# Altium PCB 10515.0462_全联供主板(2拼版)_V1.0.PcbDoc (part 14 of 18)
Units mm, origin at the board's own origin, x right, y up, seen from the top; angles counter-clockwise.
Board outline 282 x 198 mm, 2 copper layers (Top Layer, Bottom Layer); 716 components, 0 nets, 2364 pads, 1800 vias.
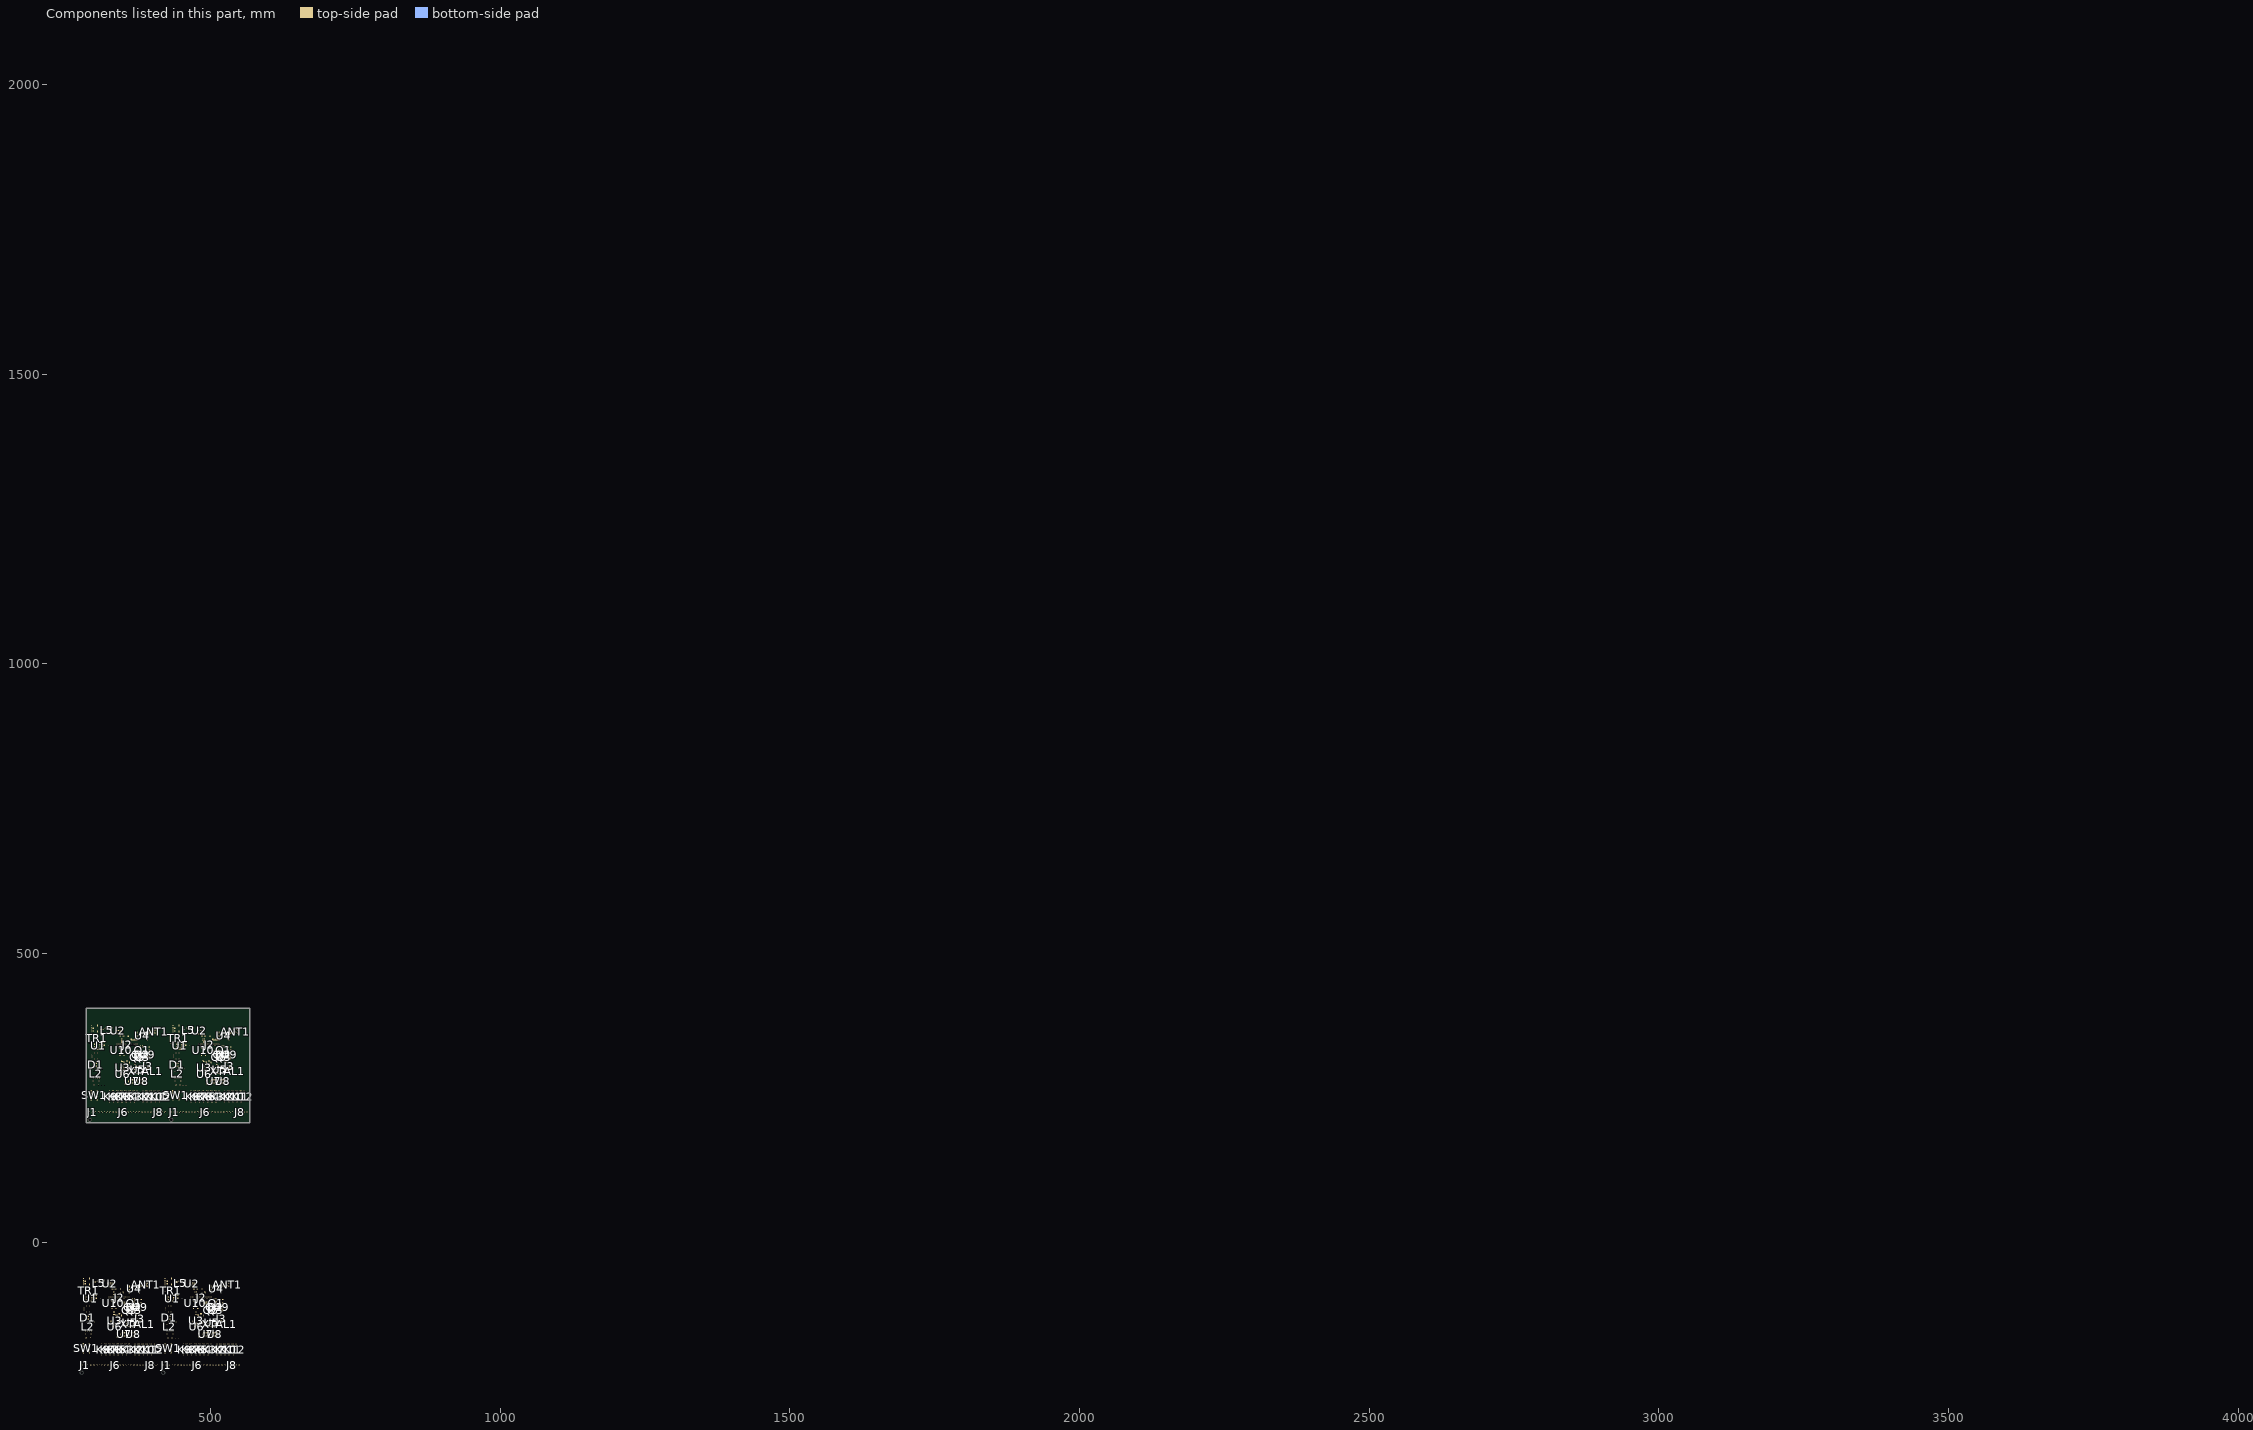
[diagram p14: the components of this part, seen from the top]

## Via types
v1: diameter 0.7, hole 0.4, Top Layer to Bottom Layer, tented both sides, 1800 vias

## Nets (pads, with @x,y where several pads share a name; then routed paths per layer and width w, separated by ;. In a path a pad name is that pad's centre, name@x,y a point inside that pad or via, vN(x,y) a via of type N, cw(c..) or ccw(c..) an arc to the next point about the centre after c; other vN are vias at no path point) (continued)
copper on no net: (continued)
  Top Layer w1.5: 440.573,-186.462 441.272,-185.763 ; 441.71,225.611 442.645,226.546 442.645,235.02 ; 442.391,371.661 444.03,371.661 445.439,373.069 ; 442.426,-218.858 443.961,-217.323 ; 442.426,-218.858 445.496,-218.858 ; 442.645,370.275 444.296,370.275 445.439,371.418 445.439,373.069 ; 442.645,370.275 445.439,373.069 ; 443.089,264.357 443.089,263.151 444.128,262.112 ; 443.089,264.357 443.089,267.088 ; 443.665,-189.256 444.764,-189.256 ; 443.875,-176.556 443.875,-173.299 ; 443.875,-176.556 444.002,-176.683 444.129,-176.683 446.288,-178.842 ; 443.875,-176.556 443.875,-174.778 ; 443.875,-176.556 448.066,-180.747 ; 443.875,-174.778 448.066,-178.969 ; 443.875,-174.778 443.875,-173.299 ; 443.875,-173.299 443.875,-164.491 ; 443.875,-164.491 444.88,-165.496 444.88,-174.016 ; 443.961,-217.323 445.496,-218.858 ; 444.128,260.42 445.566,258.982 445.566,258.515 445.693,258.642 445.693,262.96 ; 444.128,260.42 445.693,261.985 445.693,262.96 ; 444.128,260.42 444.128,267.573 ; 444.128,260.42 444.128,262.112 ; 444.128,262.112 445.058,263.042 445.058,266.643 ; 444.128,267.573 445.058,266.643 ; 444.88,-174.016 453.204,-182.34 ; 445.058,266.643 445.693,266.008 445.693,262.96 ; 445.121,-76.353 445.121,-78.361 446.034,-79.274 457.845,-79.274 459.623,-81.052 ; 445.121,-76.353 445.121,-73.489 445.971,-74.338 445.971,-76.48 ; 445.121,-76.353 445.121,-77.091 445.971,-77.94 ; 445.306,327.973 445.306,328.359 446.328,329.381 ; 445.496,-218.858 452.638,-218.858 ; 445.496,-218.858 446.247,-219.609 ; 445.802,-183.817 445.891,-183.817 447.453,-182.255 ; 445.971,-77.94 445.971,-76.48 ; 445.971,-76.48 445.971,-76.67 447.812,-78.512 458.734,-78.512 459.623,-79.401 459.623,-81.052 ; 446.247,-219.609 461.675,-219.609 ; 446.288,-178.842 447.453,-180.007 447.453,-182.255 ; 446.328,329.381 449.376,332.429 451.675,332.429 452.24,332.994 ; 446.98,272.029 447.921,271.088 451.408,271.088 452.348,272.029 ; 446.98,272.029 452.348,272.029 ; 447.59,219.145 449.749,216.986 ; 447.59,219.145 447.59,220.034 ; 447.59,220.034 447.59,225.611 447.59,225.995 447.09,225.495 447.09,218.256 448.36,216.986 449.749,216.986 ; 447.59,220.034 449.887,217.737 456.054,217.737 ; 448.066,-183.502 448.066,-180.62 ; 448.066,-183.502 450.761,-183.502 451.484,-182.779 449.325,-180.62 448.066,-180.62 ; 448.066,-180.747 448.066,-180.62 ; 448.066,-180.62 448.066,-178.969 ; 448.233,302.965 451.027,302.965 453.948,300.044 ; 448.233,302.965 449.376,302.965 452.297,300.044 453.948,300.044 ; 449.749,216.986 459.876,216.986 ; 452.638,-218.858 453.961,-217.536 ; 452.638,-218.858 455.496,-218.858 ; 453.781,-81.814 454.67,-81.814 ; 453.948,300.044 453.948,298.774 453.313,298.139 448.599,298.139 446.328,295.868 447.994,295.868 449.249,297.123 452.551,297.123 454.075,298.647 454.075,299.917 453.948,300.044 ; 453.961,-217.536 453.961,-217.323 ; 453.961,-217.323 455.496,-218.858 ; 454.202,250.133 454.9,250.832 ; 455.051,-186.252 459.856,-186.252 467.016,-186.252 474.175,-186.252 481.335,-186.252 488.495,-186.252 495.597,-186.252 495.724,-186.125 510.456,-186.125 517.568,-186.125 516.508,-185.065 ; 455.496,-218.858 462.426,-218.858 ; 456.054,217.737 457.59,219.272 ; 456.054,217.737 459.125,217.737 ; 457.294,247.339 458.393,247.339 ; 457.38,-156.871 457.38,-155.855 ; 457.504,260.039 457.504,263.296 ; 457.504,260.039 457.631,259.912 457.758,259.912 459.917,257.753 ; 457.504,260.039 457.504,261.817 ; 457.504,260.039 461.695,255.848 ; 457.504,261.817 461.695,257.626 ; 457.504,261.817 457.504,263.296 ; 457.504,263.296 457.504,272.104 ; 457.504,272.104 458.509,271.1 458.509,262.579 ; 457.59,219.272 459.125,217.737 ; 458.509,262.579 466.833,254.255 ; 458.75,360.242 458.75,358.234 459.663,357.321 471.474,357.321 473.252,355.543 ; 458.75,360.242 458.75,363.106 459.599,362.257 459.599,360.115 ; 458.75,360.242 458.75,359.504 459.599,358.655 ; 459.125,217.737 466.267,217.737 ; 459.125,217.737 459.876,216.986 ; 459.431,252.778 459.519,252.778 461.082,254.341 ; 459.599,358.655 459.599,360.115 ; 459.599,360.115 459.599,359.925 461.441,358.083 472.363,358.083 473.252,357.194 473.252,355.543 ; 459.876,216.986 475.304,216.986 ; 459.917,257.753 461.082,256.588 461.082,254.341 ; 461.675,-219.609 501.548,-219.609 ; 461.675,-219.609 462.426,-218.858 ; 461.695,253.093 461.695,255.975 ; 461.695,253.093 464.39,253.093 465.113,253.816 462.954,255.975 461.695,255.975 ; 461.695,255.848 461.695,255.975 ; 461.695,255.975 461.695,257.626 ; 462.426,-218.858 465.496,-218.858 ; 462.426,-218.858 463.961,-217.323 ; 463.433,-200.443 467.016,-196.861 467.016,-196.368 ; 463.961,-217.323 465.496,-218.858 ; 465.496,-218.858 472.426,-218.858 ; 466.267,217.737 467.59,219.06 ; 466.267,217.737 469.125,217.737 ; 467.41,354.781 468.299,354.781 ; 467.59,219.06 467.59,219.272 ; 467.59,219.272 469.125,217.737 ; 468.68,250.343 473.485,250.343 480.645,250.343 487.804,250.343 494.964,250.343 502.124,250.343 509.226,250.343 509.353,250.47 524.085,250.47 531.197,250.47 530.137,251.53 ; 469.125,217.737 476.054,217.737 ; 471.009,279.724 471.009,280.74 ; 472.426,-218.858 475.496,-218.858 ; 472.426,-218.858 473.961,-217.323 ; 473.961,-217.323 475.496,-218.858 ; 475.304,216.986 515.177,216.986 ; 475.304,216.986 476.054,217.737 ; 475.496,-218.858 482.356,-218.858 ; 476.054,217.737 479.125,217.737 ; 476.054,217.737 477.59,219.272 ; 477.062,236.152 480.645,239.735 480.645,240.227 ; 477.59,219.272 479.125,217.737 ; 479.125,217.737 486.054,217.737 ; 482.356,-218.858 485.623,-218.858 ; 482.356,-218.858 483.961,-217.254 ; 483.961,-217.254 483.961,-217.196 ; 483.961,-217.196 485.623,-218.858 ; 485.623,-218.858 492.426,-218.858 ; 486.054,217.737 489.125,217.737 ; 486.054,217.737 487.59,219.272 ; 487.59,219.272 489.125,217.737 ; 489.125,217.737 495.985,217.737 ; 492.426,-218.858 495.496,-218.858 ; 492.426,-218.858 493.961,-217.323 ; 493.961,-217.323 495.496,-218.858 ; 495.496,-218.858 502.299,-218.858 ; 495.985,217.737 499.252,217.737 ; 495.985,217.737 497.59,219.342 ; 497.59,219.342 497.59,219.399 ; 497.59,219.399 499.252,217.737 ; 499.252,217.737 506.054,217.737 ; 501.548,-219.609 506.105,-219.609 ; 501.548,-219.609 502.299,-218.858 ; 502.299,-218.858 505.355,-218.858 ; 502.299,-218.858 503.961,-217.196 ; 503.961,-217.465 503.961,-217.196 ; 503.961,-217.465 505.355,-218.858 ; 505.355,-218.858 512.235,-218.858 513.961,-217.132 ; 505.355,-218.858 506.105,-219.609 ; 506.054,217.737 509.125,217.737 ; 506.054,217.737 507.59,219.272 ; 506.105,-219.609 512.963,-219.609 513.961,-218.611 513.961,-217.132 ; 507.59,219.272 509.125,217.737 ; 509.125,217.737 515.927,217.737 ; 515.177,216.986 519.734,216.986 ; 515.177,216.986 515.927,217.737 ; 515.927,217.737 518.983,217.737 ; 515.927,217.737 517.59,219.399 ; 517.59,219.131 517.59,219.399 ; 517.59,219.131 518.983,217.737 ; 518.983,217.737 525.864,217.737 527.59,219.463 ; 518.983,217.737 519.734,216.986 ; 519.734,216.986 526.592,216.986 527.59,217.984 527.59,219.463 ; 302.338,-81.912 cw(c302.575,-82.149) 302.575,-81.814 ccw(c302.575,-82.149) 302.338,-81.912 ; 315.967,354.683 cw(c316.204,354.446) 316.204,354.781 ccw(c316.204,354.446) 315.967,354.683 ; 443.338,-81.912 cw(c443.575,-82.149) 443.575,-81.814 ccw(c443.575,-82.149) 443.338,-81.912 ; 456.967,354.683 cw(c457.204,354.446) 457.204,354.781 ccw(c457.204,354.446) 456.967,354.683
  Bottom Layer w0.2: v1@339.147,-110.212 ccw(c338.721,-109.785) 339.324,-109.785 ccw(c339.928,-109.785) v1@339.501,-110.212 ; v1@339.147,-108.661 cw(c338.721,-109.088) 339.324,-109.088 cw(c339.928,-109.088) v1@339.501,-108.661 ; v1(339.324,-110.389) v1(339.324,-108.484) ; v1@340.544,-110.212 ccw(c340.118,-109.785) 340.721,-109.785 ccw(c341.325,-109.785) v1@340.898,-110.212 ; v1@340.544,-107.899 cw(c340.118,-108.326) 340.721,-108.326 cw(c341.325,-108.326) v1@340.898,-107.899 ; v1(340.721,-110.389) v1(340.721,-107.722) ; v1@341.433,-107.391 cw(c341.007,-107.818) 341.61,-107.818 cw(c342.214,-107.818) v1@341.787,-107.391 ; 341.61,-109.962 ccw(c342.164,-109.962) v1@341.772,-110.354 ; 341.61,-109.479 ccw(c342.647,-109.479) v1@341.914,-110.212 ; v1(341.61,-107.214) 341.61,-110.262 v1(341.737,-110.389) ; v1(342.372,-107.722) 342.753,-108.103 ; v1(342.372,-91.593) 343.134,-90.831 351.605,-90.831 352.005,-90.431 352.005,-82.341 v1@352.786,-81.56 ; v1@342.372,-91.343 ccw(c342.372,-90.739) 342.799,-91.166 ccw(c343.226,-91.593) v1@342.622,-91.593 ; v1@342.393,-107.971 cw(c342.431,-108.425) 342.753,-108.103 ; v1@342.576,-111.609 ccw(c342.15,-111.182) 342.753,-111.182 ccw(c343.357,-111.182) v1@342.93,-111.609 ; v1@342.621,-107.743 ccw(c343.075,-107.781) 342.753,-108.103 ; v1(342.753,-111.786) 342.753,-108.103 ; v1@343.543,-91.872 ccw(c343.477,-91.72) 343.642,-91.72 ; v1(343.642,-92.101) 343.642,-91.72 ; v1@343.689,-92.085 cw(c344.184,-91.917) 343.815,-91.547 ; v1@343.742,-91.872 cw(c343.807,-91.72) 343.642,-91.72 ; v1@343.846,-111.609 ccw(c343.113,-110.876) 344.15,-110.876 ; v1@343.879,-92.021 cw(c344.524,-91.802) 344.042,-91.32 ; v1@343.973,-107.518 cw(c343.547,-107.945) 344.15,-107.945 cw(c344.754,-107.945) v1@344.327,-107.518 ; v1@343.988,-111.751 ccw(c343.596,-111.359) 344.15,-111.359 ; v1@344.15,-111.659 v1(344.15,-107.341) ; v1(345.547,-112.929) 345.928,-112.548 ; v1@345.568,-112.68 ccw(c345.606,-112.226) 345.928,-112.548 ; v1@345.751,-106.629 cw(c345.325,-107.056) 345.928,-107.056 cw(c346.532,-107.056) v1@346.105,-106.629 ; v1@345.796,-112.908 cw(c346.25,-112.87) 345.928,-112.548 ; v1(345.928,-106.452) 345.928,-112.548 ; v1(345.928,-92.101) 346.309,-91.72 ; v1@345.949,-91.852 ccw(c345.987,-91.398) 346.309,-91.72 ; v1@346.177,-92.08 cw(c346.631,-92.042) 346.309,-91.72 ; v1@352.409,-81.687 cw(c351.806,-81.687) 352.232,-82.114 cw(c352.659,-82.541) v1@352.659,-81.937 ; v1@352.776,326.383 ccw(c352.349,326.81) 352.953,326.81 ccw(c353.556,326.81) v1@353.13,326.383 ; v1@352.776,327.935 cw(c352.349,327.508) 352.953,327.508 cw(c353.556,327.508) v1@353.13,327.935 ; v1(352.953,326.206) v1(352.953,328.111) ; v1(353.294,-82.322) 353.04,-82.322 352.405,-82.957 352.405,-90.939 352.024,-91.32 344.042,-91.32 ; v1@353.929,-82.957 353.914,-82.972 353.152,-82.972 352.913,-83.211 352.913,-91.466 352.659,-91.72 346.309,-91.72 ; v1@354.173,326.383 ccw(c353.746,326.81) 354.35,326.81 ccw(c354.953,326.81) v1@354.527,326.383 ; v1@354.173,328.697 cw(c353.746,328.27) 354.35,328.27 cw(c354.953,328.27) v1@354.527,328.697 ; v1(354.35,326.206) v1(354.35,328.873) ; v1@355.062,329.205 cw(c354.635,328.778) 355.239,328.778 cw(c355.842,328.778) v1@355.416,329.205 ; 355.239,326.634 ccw(c355.793,326.634) v1@355.401,326.242 ; 355.239,327.117 ccw(c356.276,327.117) v1@355.543,326.383 ; v1(355.239,329.381) 355.239,326.333 v1(355.366,326.206) ; v1(356.001,328.873) 356.382,328.492 ; v1(356.001,345.002) 356.763,345.764 365.234,345.764 365.634,346.164 365.634,354.254 v1@366.415,355.035 ; v1@356.001,345.252 ccw(c356.001,345.856) 356.428,345.429 ccw(c356.854,345.002) v1@356.251,345.002 ; v1@356.022,328.624 cw(c356.06,328.17) 356.382,328.493 ; v1@356.205,324.986 ccw(c355.778,325.413) 356.382,325.413 ccw(c356.985,325.413) v1@356.559,324.986 ; v1@356.25,328.853 ccw(c356.704,328.815) 356.382,328.493 ; v1(356.382,324.809) 356.382,328.492 ; v1@357.171,344.724 ccw(c357.106,344.875) 357.271,344.875 ccw(c357.436,344.875) v1@357.37,344.724 ; v1(357.271,344.494) 357.271,344.875 357.671,345.275 ; v1@357.318,344.511 cw(c357.813,344.679) 357.444,345.048 ; v1@357.475,324.986 ccw(c356.742,325.72) 357.779,325.72 ; v1@357.508,344.575 cw(c358.152,344.794) 357.671,345.275 ; v1@357.602,329.078 cw(c357.175,328.651) 357.779,328.651 cw(c358.382,328.651) v1@357.956,329.078 ; v1@357.617,324.845 ccw(c357.225,325.237) 357.779,325.237 ; v1@357.779,324.936 v1(357.779,329.254) ; v1(359.176,323.666) 359.557,324.047 v1(359.557,330.143) ; v1@359.197,323.916 ccw(c359.235,324.37) 359.557,324.047 ccw(c359.879,323.725) v1@359.425,323.687 ; v1@359.38,329.967 cw(c358.953,329.54) 359.557,329.54 cw(c360.16,329.54) v1@359.734,329.967 ; v1(359.557,344.494) 359.938,344.875 366.288,344.875 366.542,345.129 366.542,353.384 366.781,353.623 367.543,353.623 v1@367.558,353.638 ; v1@359.578,344.744 ccw(c359.616,345.198) 359.938,344.875 ccw(c360.26,344.553) v1@359.806,344.515 ; v1(365.613,-133.122) 366.263,-132.472 375.28,-132.472 375.515,-132.237 ; v1@365.613,-132.872 ccw(c365.613,-132.268) 366.04,-132.695 ccw(c366.467,-133.122) v1@365.863,-133.122 ; v1@366.038,354.908 cw(c365.434,354.908) 365.861,354.482 cw(c366.288,354.055) v1@366.288,354.658 ; v1@366.806,-133.299 cw(c367.233,-133.726) 367.233,-133.122 cw(c367.233,-132.518) v1@366.806,-132.945 ; v1@366.913,-133.122 379.075,-133.122 379.515,-132.682 ; v1(366.923,354.273) 366.669,354.273 366.034,353.638 366.034,345.656 365.653,345.275 357.671,345.275 ; v1(374.884,-116.104) v1(377.24,-116.104) ; 375.011,-127.267 375.011,-127.218 375.457,-126.772 ; v1@375.061,-116.281 cw(c375.488,-116.708) 375.488,-116.104 cw(c375.488,-115.5) v1@375.061,-115.927 ; 375.225,-131.781 cw(c375.012,-132.237) 375.515,-132.237 ; v1@375.281,-119.964 cw(c374.854,-120.391) 375.457,-120.391 cw(c376.061,-120.391) v1@375.634,-119.964 ; 375.457,-126.961 375.457,-126.772 ; v1(375.457,-119.787) 375.457,-126.772 ; 375.515,-131.285 375.515,-132.237 ; 375.805,-131.781 ccw(c376.018,-132.237) 375.515,-132.237 ; 376.027,-127.267 375.952,-127.267 375.457,-126.772 ; v1(377.043,-119.787) 379.329,-119.787 v1(381.615,-119.787) ; v1@377.063,-116.281 ccw(c376.636,-116.708) 376.636,-116.104 ccw(c376.636,-115.5) v1@377.063,-115.927 ; v1@377.22,-119.964 cw(c377.647,-120.391) 377.647,-119.787 cw(c377.647,-119.183) v1@377.22,-119.61 ; 379.06,-131.674 cw(c378.17,-132.682) 379.515,-132.682 ; 379.192,-131.524 cw(c378.561,-132.239) 379.515,-132.239 cw(c380.469,-132.239) 379.838,-131.524 ; v1(379.242,303.473) 379.892,304.123 388.909,304.123 389.144,304.358 ; v1@379.242,303.723 ccw(c379.242,304.327) 379.669,303.9 ccw(c380.095,303.473) v1@379.492,303.473 ; 379.515,-131.285 379.515,-132.682 ; 379.97,-131.674 ccw(c380.86,-132.682) 379.515,-132.682 ; v1@380.435,303.297 cw(c380.861,302.87) 380.861,303.473 cw(c380.861,304.077) v1@380.435,303.65 ; v1@380.542,303.473 392.704,303.473 393.144,303.913 ; v1@381.438,-119.964 ccw(c381.012,-120.391) 381.012,-119.787 ccw(c381.012,-119.183) v1@381.438,-119.61 ; v1(388.513,320.491) v1(390.868,320.491) ; 388.64,309.328 388.64,309.377 389.086,309.823 ; v1@388.69,320.315 cw(c389.116,319.888) 389.116,320.491 cw(c389.116,321.095) v1@388.69,320.668 ; 388.853,304.814 cw(c388.641,304.358) 389.144,304.358 ; v1@388.909,316.632 cw(c388.483,316.205) 389.086,316.205 cw(c389.69,316.205) v1@389.263,316.632 ; 389.086,309.635 389.086,309.823 ; v1(389.086,316.808) 389.086,309.823 ; 389.144,305.31 389.144,304.358 ; 389.434,304.814 ccw(c389.646,304.358) 389.144,304.358 ; 389.656,309.328 389.581,309.328 389.086,309.823 ; v1(390.672,316.808) 392.958,316.808 v1(395.244,316.808) ; v1@390.692,320.315 ccw(c390.265,319.888) 390.265,320.491 ccw(c390.265,321.095) v1@390.692,320.668 ; v1@390.849,316.632 cw(c391.275,316.205) 391.275,316.808 cw(c391.275,317.412) v1@390.849,316.985 ; 392.689,304.922 cw(c391.799,303.913) 393.144,303.913 ; 392.821,305.072 cw(c392.19,304.357) 393.144,304.357 cw(c394.097,304.357) 393.466,305.072 ; 393.144,305.31 393.144,303.913 ; 393.599,304.922 ccw(c394.489,303.913) 393.144,303.913 ; v1@395.067,316.632 ccw(c394.64,316.205) 394.64,316.808 ccw(c394.64,317.412) v1@395.067,316.985 ; v1@480.147,-110.212 ccw(c479.721,-109.785) 480.324,-109.785 ccw(c480.928,-109.785) v1@480.501,-110.212 ; v1@480.147,-108.661 cw(c479.721,-109.088) 480.324,-109.088 cw(c480.928,-109.088) v1@480.501,-108.661 ; v1(480.324,-110.389) v1(480.324,-108.484) ; v1@481.544,-110.212 ccw(c481.118,-109.785) 481.721,-109.785 ccw(c482.325,-109.785) v1@481.898,-110.212 ; v1@481.544,-107.899 cw(c481.118,-108.326) 481.721,-108.326 cw(c482.325,-108.326) v1@481.898,-107.899 ; v1(481.721,-110.389) v1(481.721,-107.722) ; v1@482.433,-107.391 cw(c482.007,-107.818) 482.61,-107.818 cw(c483.214,-107.818) v1@482.787,-107.391 ; 482.61,-109.962 ccw(c483.164,-109.962) v1@482.772,-110.354 ; 482.61,-109.479 ccw(c483.647,-109.479) v1@482.914,-110.212 ; v1(482.61,-107.214) 482.61,-110.262 v1(482.737,-110.389) ; v1(483.372,-107.722) 483.753,-108.103 ; v1(483.372,-91.593) 484.134,-90.831 492.605,-90.831 493.005,-90.431 493.005,-82.341 v1@493.786,-81.56 ; v1@483.372,-91.343 ccw(c483.372,-90.739) 483.799,-91.166 ccw(c484.226,-91.593) v1@483.622,-91.593 ; v1@483.393,-107.971 cw(c483.431,-108.425) 483.753,-108.103 ; v1@483.576,-111.609 ccw(c483.15,-111.182) 483.753,-111.182 ccw(c484.357,-111.182) v1@483.93,-111.609 ; v1@483.621,-107.743 ccw(c484.075,-107.781) 483.753,-108.103 ; v1(483.753,-111.786) 483.753,-108.103 ; v1@484.543,-91.872 ccw(c484.477,-91.72) 484.642,-91.72 ; v1(484.642,-92.101) 484.642,-91.72 ; v1@484.689,-92.085 cw(c485.184,-91.917) 484.815,-91.547 ; v1@484.742,-91.872 cw(c484.807,-91.72) 484.642,-91.72 ; v1@484.846,-111.609 ccw(c484.113,-110.876) 485.15,-110.876 ; v1@484.879,-92.021 cw(c485.524,-91.802) 485.042,-91.32 ; v1@484.973,-107.518 cw(c484.547,-107.945) 485.15,-107.945 cw(c485.754,-107.945) v1@485.327,-107.518 ; v1@484.988,-111.751 ccw(c484.596,-111.359) 485.15,-111.359 ; v1@485.15,-111.659 v1(485.15,-107.341) ; v1(486.547,-112.929) 486.928,-112.548 ; v1@486.568,-112.68 ccw(c486.606,-112.226) 486.928,-112.548 ; v1@486.751,-106.629 cw(c486.325,-107.056) 486.928,-107.056 cw(c487.532,-107.056) v1@487.105,-106.629 ; v1@486.796,-112.908 cw(c487.25,-112.87) 486.928,-112.548 ; v1(486.928,-106.452) 486.928,-112.548 ; v1(486.928,-92.101) 487.309,-91.72 ; v1@486.949,-91.852 ccw(c486.987,-91.398) 487.309,-91.72 ; v1@487.177,-92.08 cw(c487.631,-92.042) 487.309,-91.72 ; v1@493.409,-81.687 cw(c492.806,-81.687) 493.232,-82.114 cw(c493.659,-82.541) v1@493.659,-81.937 ; v1@493.776,326.383 ccw(c493.349,326.81) 493.953,326.81 ccw(c494.556,326.81) v1@494.13,326.383 ; v1@493.776,327.935 cw(c493.349,327.508) 493.953,327.508 cw(c494.556,327.508) v1@494.13,327.935 ; v1(493.953,326.206) v1(493.953,328.111) ; v1(494.294,-82.322) 494.04,-82.322 493.405,-82.957 493.405,-90.939 493.024,-91.32 485.042,-91.32 ; v1@494.929,-82.957 494.914,-82.972 494.152,-82.972 493.913,-83.211 493.913,-91.466 493.659,-91.72 487.309,-91.72 ; v1@495.173,326.383 ccw(c494.746,326.81) 495.35,326.81 ccw(c495.953,326.81) v1@495.527,326.383 ; v1@495.173,328.697 cw(c494.746,328.27) 495.35,328.27 cw(c495.953,328.27) v1@495.527,328.697 ; v1(495.35,326.206) v1(495.35,328.873) ; v1@496.062,329.205 cw(c495.635,328.778) 496.239,328.778 cw(c496.842,328.778) v1@496.416,329.205 ; 496.239,326.634 ccw(c496.793,326.634) v1@496.401,326.242 ; 496.239,327.117 ccw(c497.276,327.117) v1@496.543,326.383 ; v1(496.239,329.381) 496.239,326.333 v1(496.366,326.206) ; v1(497.001,328.873) 497.382,328.492 ; v1(497.001,345.002) 497.763,345.764 506.234,345.764 506.634,346.164 506.634,354.254 v1@507.415,355.035 ; v1@497.001,345.252 ccw(c497.001,345.856) 497.428,345.429 ccw(c497.854,345.002) v1@497.251,345.002 ; v1@497.022,328.624 cw(c497.06,328.17) 497.382,328.493 ; v1@497.205,324.986 ccw(c496.778,325.413) 497.382,325.413 ccw(c497.985,325.413) v1@497.559,324.986 ; v1@497.25,328.853 ccw(c497.704,328.815) 497.382,328.493 ; v1(497.382,324.809) 497.382,328.492 ; v1@498.171,344.724 ccw(c498.106,344.875) 498.271,344.875 ccw(c498.436,344.875) v1@498.37,344.724 ; v1(498.271,344.494) 498.271,344.875 498.671,345.275 ; v1@498.318,344.511 cw(c498.813,344.679) 498.444,345.048 ; v1@498.475,324.986 ccw(c497.742,325.72) 498.779,325.72 ; v1@498.508,344.575 cw(c499.152,344.794) 498.671,345.275 ; v1@498.602,329.078 cw(c498.175,328.651) 498.779,328.651 cw(c499.382,328.651) v1@498.956,329.078 ; v1@498.617,324.845 ccw(c498.225,325.237) 498.779,325.237 ; v1@498.779,324.936 v1(498.779,329.254) ; v1(500.176,323.666) 500.557,324.047 v1(500.557,330.143) ; v1@500.197,323.916 ccw(c500.235,324.37) 500.557,324.047 ccw(c500.879,323.725) v1@500.425,323.687 ; v1@500.38,329.967 cw(c499.953,329.54) 500.557,329.54 cw(c501.16,329.54) v1@500.734,329.967 ; v1(500.557,344.494) 500.938,344.875 507.288,344.875 507.542,345.129 507.542,353.384 507.781,353.623 508.543,353.623 v1@508.558,353.638 ; v1@500.578,344.744 ccw(c500.616,345.198) 500.938,344.875 ccw(c501.26,344.553) v1@500.806,344.515 ; v1(506.613,-133.122) 507.263,-132.472 516.28,-132.472 516.515,-132.237 ; v1@506.613,-132.872 ccw(c506.613,-132.268) 507.04,-132.695 ccw(c507.467,-133.122) v1@506.863,-133.122 ; v1@507.038,354.908 cw(c506.434,354.908) 506.861,354.482 cw(c507.288,354.055) v1@507.288,354.658 ; v1@507.806,-133.299 cw(c508.233,-133.726) 508.233,-133.122 cw(c508.233,-132.518) v1@507.806,-132.945 ; v1@507.913,-133.122 520.075,-133.122 520.515,-132.682 ; v1(507.923,354.273) 507.669,354.273 507.034,353.638 507.034,345.656 506.653,345.275 498.671,345.275 ; v1(515.884,-116.104) v1(518.24,-116.104) ; 516.011,-127.267 516.011,-127.218 516.457,-126.772 ; v1@516.061,-116.281 cw(c516.488,-116.708) 516.488,-116.104 cw(c516.488,-115.5) v1@516.061,-115.927 ; 516.225,-131.781 cw(c516.012,-132.237) 516.515,-132.237 ; v1@516.281,-119.964 cw(c515.854,-120.391) 516.457,-120.391 cw(c517.061,-120.391) v1@516.634,-119.964 ; 516.457,-126.961 516.457,-126.772 ; v1(516.457,-119.787) 516.457,-126.772 ; 516.515,-131.285 516.515,-132.237 ; 516.805,-131.781 ccw(c517.018,-132.237) 516.515,-132.237 ; 517.027,-127.267 516.952,-127.267 516.457,-126.772 ; v1(518.043,-119.787) 520.329,-119.787 v1(522.615,-119.787) ; v1@518.063,-116.281 ccw(c517.636,-116.708) 517.636,-116.104 ccw(c517.636,-115.5) v1@518.063,-115.927 ; v1@518.22,-119.964 cw(c518.647,-120.391) 518.647,-119.787 cw(c518.647,-119.183) v1@518.22,-119.61 ; 520.06,-131.674 cw(c519.17,-132.682) 520.515,-132.682 ; 520.192,-131.524 cw(c519.561,-132.239) 520.515,-132.239 cw(c521.469,-132.239) 520.838,-131.524 ; v1(520.242,303.473) 520.892,304.123 529.909,304.123 530.144,304.358 ; v1@520.242,303.723 ccw(c520.242,304.327) 520.669,303.9 ccw(c521.095,303.473) v1@520.492,303.473 ; 520.515,-131.285 520.515,-132.682 ; 520.97,-131.674 ccw(c521.86,-132.682) 520.515,-132.682 ; v1@521.435,303.297 cw(c521.861,302.87) 521.861,303.473 cw(c521.861,304.077) v1@521.435,303.65 ; v1@521.542,303.473 533.704,303.473 534.144,303.913 ; v1@522.438,-119.964 ccw(c522.012,-120.391) 522.012,-119.787 ccw(c522.012,-119.183) v1@522.438,-119.61 ; v1(529.513,320.491) v1(531.868,320.491) ; 529.64,309.328 529.64,309.377 530.086,309.823 ; v1@529.69,320.315 cw(c530.116,319.888) 530.116,320.491 cw(c530.116,321.095) v1@529.69,320.668 ; 529.853,304.814 cw(c529.641,304.358) 530.144,304.358 ; v1@529.909,316.632 cw(c529.483,316.205) 530.086,316.205 cw(c530.69,316.205) v1@530.263,316.632 ; 530.086,309.635 530.086,309.823 ; v1(530.086,316.808) 530.086,309.823 ; 530.144,305.31 530.144,304.358 ; 530.434,304.814 ccw(c530.646,304.358) 530.144,304.358 ; 530.656,309.328 530.581,309.328 530.086,309.823 ; v1(531.672,316.808) 533.958,316.808 v1(536.244,316.808) ; v1@531.692,320.315 ccw(c531.265,319.888) 531.265,320.491 ccw(c531.265,321.095) v1@531.692,320.668 ; v1@531.849,316.632 cw(c532.275,316.205) 532.275,316.808 cw(c532.275,317.412) v1@531.849,316.985 ; 533.689,304.922 cw(c532.799,303.913) 534.144,303.913 ; 533.821,305.072 cw(c533.19,304.357) 534.144,304.357 cw(c535.097,304.357) 534.466,305.072 ; 534.144,305.31 534.144,303.913 ; 534.599,304.922 ccw(c535.489,303.913) 534.144,303.913 ; v1@536.067,316.632 ccw(c535.64,316.205) 535.64,316.808 ccw(c535.64,317.412) v1@536.067,316.985 ; 343.642,-91.72 344.042,-91.32 ; 484.642,-91.72 485.042,-91.32
  Bottom Layer w0.3: v1(329.545,-132.36) 347.833,-132.36 348.341,-131.852 v1(348.341,-129.439) ; v1@329.687,-132.501 cw(c330.028,-132.843) 330.028,-132.36 cw(c330.028,-131.877) v1@329.687,-132.219 ; v1(343.174,304.235) 361.462,304.235 361.97,304.743 v1(361.97,307.156) ; v1@343.315,304.094 cw(c343.657,303.753) 343.657,304.235 cw(c343.657,304.718) v1@343.315,304.377 ; v1@348.2,-129.58 cw(c347.858,-129.922) 348.341,-129.922 cw(c348.824,-129.922) v1@348.483,-129.58 ; v1@361.828,307.015 cw(c361.487,306.674) 361.97,306.674 cw(c362.453,306.674) v1@362.111,307.015 ; v1(470.545,-132.36) 488.833,-132.36 489.341,-131.852 v1(489.341,-129.439) ; v1@470.687,-132.501 cw(c471.028,-132.843) 471.028,-132.36 cw(c471.028,-131.877) v1@470.687,-132.219 ; v1(484.174,304.235) 502.462,304.235 502.97,304.743 v1(502.97,307.156) ; v1@484.315,304.094 cw(c484.657,303.753) 484.657,304.235 cw(c484.657,304.718) v1@484.315,304.377 ; v1@489.2,-129.58 cw(c488.858,-129.922) 489.341,-129.922 cw(c489.824,-129.922) v1@489.483,-129.58 ; v1@502.828,307.015 cw(c502.487,306.674) 502.97,306.674 cw(c503.453,306.674) v1@503.111,307.015
  Bottom Layer w0.45: v1(323.195,-70.892) 323.335,-71.032 326.31,-71.032 328.355,-68.987 v1(328.656,-68.987) ; v1@323.284,-70.804 ccw(c323.835,-70.252) 323.835,-71.032 ; v1(324.211,-67.717) 325.608,-67.717 325.989,-68.098 v1(325.989,-70.257) ; 327.929,-69.413 cw(c328.656,-70.14) v1@328.656,-69.112 ; v1@328.694,-69.008 v1(333.101,-69.008) ; v1@328.745,-68.899 ccw(c329.01,-68.634) 329.01,-69.008 ; v1(329.672,-136.193) 336.172,-136.193 336.694,-136.715 v1(336.694,-138.112) ; 333.491,-136.193 v1(333.491,-134.13) 333.491,-133.368 333.661,-133.197 v1(342.447,-133.197) ; v1@336.53,-140.234 347.833,-140.234 348.722,-141.123 350.528,-141.123 v1(350.895,-141.49) 348.708,-141.49 347.706,-140.488 v1(336.403,-140.488) 336.657,-140.234 ; v1(336.824,365.703) 336.964,365.563 339.939,365.563 341.984,367.608 v1(342.285,367.608) ; v1@336.912,365.792 ccw(c337.464,366.343) 337.464,365.563 ; v1(337.84,368.878) 339.237,368.878 339.618,368.497 v1(339.618,366.338) ; 341.558,367.182 cw(c342.285,366.455) v1@342.285,367.483 ; v1@342.323,367.587 v1(346.73,367.587) ; v1@342.373,367.697 ccw(c342.638,367.962) 342.638,367.587 ; v1(343.301,300.403) 349.801,300.403 350.323,299.881 v1(350.323,298.484) ; v1@345.928,-126.645 345.928,-126.899 346.309,-127.28 v1(352.278,-127.28) v1(355.072,-127.28) v1@363.547,-127.28 ; 346.944,-127.28 346.436,-126.772 v1(345.928,-126.772) 346.182,-127.026 362.819,-127.026 ; 347.119,300.403 v1(347.119,302.466) 347.119,303.228 347.29,303.399 v1(356.076,303.399) ; 349.707,-141.123 cw(c349.707,-142.678) v1@350.807,-141.578 ; v1@350.159,296.361 361.462,296.361 362.351,295.472 364.157,295.472 v1(364.524,295.105) 362.337,295.105 361.335,296.107 v1(350.032,296.107) 350.286,296.361 ; 351.897,-134.164 cw(c353.066,-134.164) v1@352.24,-133.337 ; 352.024,-128.155 352.15,-128.155 352.926,-128.931 ; 352.138,-143.001 352.138,-142.62 ; v1(352.151,-133.249) v1@352.138,-133.262 ; 352.926,-128.155 352.926,-128.931 ; 353.675,-142.406 353.415,-142.145 ; 353.675,-128.282 353.026,-128.931 352.926,-128.931 ; 355.162,-142.145 cw(c355.162,-142.949) v1@355.73,-142.381 ; 355.242,-142.406 ccw(c355.242,-141.716) v1@355.73,-142.204 ; v1@355.906,-142.381 cw(c356.474,-142.949) 356.474,-142.145 ; v1@355.906,-142.204 ccw(c356.394,-141.716) 356.394,-142.406 ; 358.441,-142.406 353.18,-142.406 352.926,-142.152 352.926,-141.377 ; 358.454,-142.393 365.486,-142.393 366.003,-142.909 366.003,-147.084 ; v1@359.557,309.95 359.557,309.696 359.938,309.315 v1(365.907,309.315) v1(368.701,309.315) v1@377.176,309.315 ; 360.573,309.315 360.065,309.823 v1(359.557,309.823) 359.811,309.569 376.448,309.569 ; v1(362.679,-122.073) v1@362.679,-117.813 ; v1@362.941,-151.002 cw(c363.796,-151.856) 363.796,-150.648 ; 363.336,295.472 cw(c363.336,293.918) v1@364.435,295.017 ; v1(363.581,-127.28) 363.327,-127.026 362.819,-127.026 ; v1@363.594,-127.267 380.218,-127.267 380.332,-127.267 ; 364.851,-148.568 cw(c366.454,-148.568) v1@365.321,-147.434 ; 364.851,-147.885 cw(c365.266,-147.885) v1@365.24,-147.471 ; v1(365.105,-144.425) 365.105,-143.536 364.71,-143.141 352.659,-143.141 ; v1(365.105,-139.091) 376.281,-139.091 v1(376.789,-139.599) ; v1@365.11,-147.647 ccw(c365.253,-147.294) 365.523,-147.564 ; v1@365.279,-147.23 ccw(c365.53,-146.611) 366.003,-147.084 ; 365.526,302.432 cw(c366.695,302.432) v1@365.868,303.258 ; 365.613,-148.108 366.248,-147.473 366.248,-142.647 365.747,-142.145 353.415,-142.145 ; 365.653,308.44 365.779,308.44 366.555,307.664 ; 365.767,293.594 365.767,293.975 ; v1(365.78,303.346) v1@365.767,303.333 ; 365.88,-142.787 365.88,-146.698 v1(365.232,-147.346) ; 366.555,308.44 366.555,307.664 ; 367.304,294.189 367.043,294.45 ; 367.304,308.313 366.655,307.664 366.555,307.664 ; 368.703,-127.267 ccw(c368.703,-126.576) v1@369.192,-127.065 ; 368.79,294.45 cw(c368.79,293.647) v1@369.358,294.215 ; 368.871,294.189 ccw(c368.871,294.879) v1@369.358,294.391 ; v1(369.28,-127.153) 381.107,-127.153 381.515,-127.561 ; v1@369.368,-127.065 ccw(c369.857,-126.576) 369.857,-127.267 ; v1@369.535,294.215 cw(c370.103,293.647) 370.103,294.45 ; v1@369.535,294.391 ccw(c370.023,294.879) 370.023,294.189 ; 372.07,294.189 366.809,294.189 366.555,294.443 366.555,295.218 ; 372.083,294.202 379.115,294.202 379.631,293.686 379.631,289.512 ; v1@375.354,-101.538 ccw(c375.873,-101.018) 375.873,-101.753 ; v1@375.392,-101.753 v1(380.091,-101.753) ; v1(376.308,314.522) v1@376.308,318.782 ; v1@376.57,285.594 cw(c377.424,284.74) 377.424,285.947 ; v1(377.21,309.315) 376.956,309.569 376.448,309.569 ; v1@377.223,309.328 393.847,309.328 393.961,309.328 ; 378.48,288.028 cw(c380.082,288.028) v1@378.949,289.161 ; 378.48,288.711 cw(c378.895,288.711) v1@378.869,289.125 ; v1(378.734,292.17) 378.734,293.059 378.339,293.454 366.288,293.454 ; v1(378.734,297.504) 389.91,297.504 v1(390.418,296.996) ; v1@378.739,288.948 ccw(c378.882,289.301) 379.151,289.032 ; v1(378.884,-110.635) v1@380.464,-110.635 ; v1@378.908,289.365 ccw(c379.159,289.984) 379.631,289.512 ; 379.242,288.487 379.877,289.122 379.877,293.948 379.375,294.45 367.043,294.45 ; 379.509,293.808 379.509,289.897 v1(378.861,289.249) ; 381.117,-130.761 ccw(c380.157,-129.801) 381.515,-129.801 ccw(c382.873,-129.801) 381.913,-130.761 cw(c383.551,-129.123) 381.234,-129.123 ; 381.234,-130.878 381.234,-128.169 380.332,-127.267 ; 381.234,-130.209 ccw(c382.464,-130.209) 381.594,-131.079 ; 381.515,-131.285 381.515,-131.158 381.515,-127.942 ; 382.332,309.328 ccw(c382.332,310.019) v1@382.82,309.531 ; v1(382.909,309.442) 394.736,309.442 395.144,309.035 ; v1@382.997,309.531 ccw(c383.486,310.019) 383.486,309.328 ; v1@388.982,335.058 ccw(c389.502,335.578) 389.502,334.842 ; v1@389.021,334.842 v1(393.72,334.842) ; v1(392.513,325.961) v1@394.092,325.961 ; 394.746,305.835 ccw(c393.786,306.795) 395.144,306.795 ccw(c396.502,306.795) 395.541,305.835 cw(c397.18,307.473) 394.863,307.473 ; 394.863,305.718 394.863,308.426 393.961,309.328 ; 394.863,306.387 ccw(c396.093,306.387) 395.223,305.517 ; 395.144,305.31 395.144,305.437 395.144,308.654 ; v1(464.195,-70.892) 464.335,-71.032 467.31,-71.032 469.355,-68.987 v1(469.656,-68.987) ; v1@464.284,-70.804 ccw(c464.835,-70.252) 464.835,-71.032 ; v1(465.211,-67.717) 466.608,-67.717 466.989,-68.098 v1(466.989,-70.257) ; 468.929,-69.413 cw(c469.656,-70.14) v1@469.656,-69.112 ; v1@469.694,-69.008 v1(474.101,-69.008) ; v1@469.745,-68.899 ccw(c470.01,-68.634) 470.01,-69.008 ; v1(470.672,-136.193) 477.172,-136.193 477.694,-136.715 v1(477.694,-138.112) ; 474.491,-136.193 v1(474.491,-134.13) 474.491,-133.368 474.661,-133.197 v1(483.447,-133.197) ; v1@477.53,-140.234 488.833,-140.234 489.722,-141.123 491.528,-141.123 v1(491.895,-141.49) 489.708,-141.49 488.706,-140.488 v1(477.403,-140.488) 477.657,-140.234 ; v1(477.824,365.703) 477.964,365.563 480.939,365.563 482.984,367.608 v1(483.285,367.608) ; v1@477.912,365.792 ccw(c478.464,366.343) 478.464,365.563 ; v1(478.84,368.878) 480.237,368.878 480.618,368.497 v1(480.618,366.338) ; 482.558,367.182 cw(c483.285,366.455) v1@483.285,367.483 ; v1@483.323,367.587 v1(487.73,367.587) ; v1@483.373,367.697 ccw(c483.638,367.962) 483.638,367.587 ; v1(484.301,300.403) 490.801,300.403 491.323,299.881 v1(491.323,298.484) ; v1@486.928,-126.645 486.928,-126.899 487.309,-127.28 v1(493.278,-127.28) v1(496.072,-127.28) v1@504.547,-127.28 ; 487.944,-127.28 487.436,-126.772 v1(486.928,-126.772) 487.182,-127.026 503.819,-127.026 ; 488.119,300.403 v1(488.119,302.466) 488.119,303.228 488.29,303.399 v1(497.076,303.399) ; 490.707,-141.123 cw(c490.707,-142.678) v1@491.807,-141.578 ; v1@491.159,296.361 502.462,296.361 503.351,295.472 505.157,295.472 v1(505.524,295.105) 503.337,295.105 502.335,296.107 v1(491.032,296.107) 491.286,296.361 ; 492.897,-134.164 cw(c494.066,-134.164) v1@493.24,-133.337 ; 493.024,-128.155 493.15,-128.155 493.926,-128.931 ; 493.138,-143.001 493.138,-142.62 ; v1(493.151,-133.249) v1@493.138,-133.262 ; 493.926,-128.155 493.926,-128.931 ; 494.675,-142.406 494.415,-142.145 ; 494.675,-128.282 494.026,-128.931 493.926,-128.931 ; 496.162,-142.145 cw(c496.162,-142.949) v1@496.73,-142.381 ; 496.242,-142.406 ccw(c496.242,-141.716) v1@496.73,-142.204 ; v1@496.906,-142.381 cw(c497.474,-142.949) 497.474,-142.145 ; v1@496.906,-142.204 ccw(c497.394,-141.716) 497.394,-142.406 ; 499.441,-142.406 494.18,-142.406 493.926,-142.152 493.926,-141.377 ; 499.454,-142.393 506.486,-142.393 507.003,-142.909 507.003,-147.084 ; v1@500.557,309.95 500.557,309.696 500.938,309.315 v1(506.907,309.315) v1(509.701,309.315) v1@518.176,309.315 ; 501.573,309.315 501.065,309.823 v1(500.557,309.823) 500.811,309.569 517.448,309.569 ; v1(503.679,-122.073) v1@503.679,-117.813 ; v1@503.941,-151.002 cw(c504.796,-151.856) 504.796,-150.648 ; 504.336,295.472 cw(c504.336,293.918) v1@505.435,295.017 ; v1(504.581,-127.28) 504.327,-127.026 503.819,-127.026 ; v1@504.594,-127.267 521.218,-127.267 521.332,-127.267 ; 505.851,-148.568 cw(c507.454,-148.568) v1@506.321,-147.434 ; 505.851,-147.885 cw(c506.266,-147.885) v1@506.24,-147.471 ; v1(506.105,-144.425) 506.105,-143.536 505.71,-143.141 493.659,-143.141 ; v1(506.105,-139.091) 517.281,-139.091 v1(517.789,-139.599) ; v1@506.11,-147.647 ccw(c506.253,-147.294) 506.523,-147.564 ; v1@506.279,-147.23 ccw(c506.53,-146.611) 507.003,-147.084 ; 506.526,302.432 cw(c507.695,302.432) v1@506.868,303.258 ; 506.613,-148.108 507.248,-147.473 507.248,-142.647 506.747,-142.145 494.415,-142.145 ; 506.653,308.44 506.779,308.44 507.555,307.664 ; 506.767,293.594 506.767,293.975 ; v1(506.78,303.346) v1@506.767,303.333 ; 506.88,-142.787 506.88,-146.698 v1(506.232,-147.346) ; 507.555,308.44 507.555,307.664 ; 508.304,294.189 508.043,294.45 ; 508.304,308.313 507.655,307.664 507.555,307.664 ; 509.703,-127.267 ccw(c509.703,-126.576) v1@510.192,-127.065 ; 509.79,294.45 cw(c509.79,293.647) v1@510.358,294.215 ; 509.871,294.189 ccw(c509.871,294.879) v1@510.358,294.391 ; v1(510.28,-127.153) 522.107,-127.153 522.515,-127.561 ; v1@510.368,-127.065 ccw(c510.857,-126.576) 510.857,-127.267 ; v1@510.535,294.215 cw(c511.103,293.647) 511.103,294.45 ; v1@510.535,294.391 ccw(c511.023,294.879) 511.023,294.189 ; 513.07,294.189 507.809,294.189 507.555,294.443 507.555,295.218 ; 513.083,294.202 520.115,294.202 520.631,293.686 520.631,289.512 ; v1@516.354,-101.538 ccw(c516.873,-101.018) 516.873,-101.753 ; v1@516.392,-101.753 v1(521.091,-101.753) ; v1(517.308,314.522) v1@517.308,318.782 ; v1@517.57,285.594 cw(c518.424,284.74) 518.424,285.947 ; v1(518.21,309.315) 517.956,309.569 517.448,309.569 ; v1@518.223,309.328 534.847,309.328 534.961,309.328 ; 519.48,288.028 cw(c521.082,288.028) v1@519.949,289.161 ; 519.48,288.711 cw(c519.895,288.711) v1@519.869,289.125 ; v1(519.734,292.17) 519.734,293.059 519.339,293.454 507.288,293.454 ; v1(519.734,297.504) 530.91,297.504 v1(531.418,296.996) ; v1@519.739,288.948 ccw(c519.882,289.301) 520.151,289.032 ; v1(519.884,-110.635) v1@521.464,-110.635 ; v1@519.908,289.365 ccw(c520.159,289.984) 520.631,289.512 ; 520.242,288.487 520.877,289.122 520.877,293.948 520.375,294.45 508.043,294.45 ; 520.509,293.808 520.509,289.897 v1(519.861,289.249) ; 522.117,-130.761 ccw(c521.157,-129.801) 522.515,-129.801 ccw(c523.873,-129.801) 522.913,-130.761 cw(c524.551,-129.123) 522.234,-129.123 ; 522.234,-130.878 522.234,-128.169 521.332,-127.267 ; 522.234,-130.209 ccw(c523.464,-130.209) 522.594,-131.079 ; 522.515,-131.285 522.515,-131.158 522.515,-127.942 ; 523.332,309.328 ccw(c523.332,310.019) v1@523.82,309.531 ; v1(523.909,309.442) 535.736,309.442 536.144,309.035 ; v1@523.997,309.531 ccw(c524.486,310.019) 524.486,309.328 ; v1@529.982,335.058 ccw(c530.502,335.578) 530.502,334.842 ; v1@530.021,334.842 v1(534.72,334.842) ; v1(533.513,325.961) v1@535.092,325.961 ; 535.746,305.835 ccw(c534.786,306.795) 536.144,306.795 ccw(c537.502,306.795) 536.541,305.835 cw(c538.18,307.473) 535.863,307.473 ; 535.863,305.718 535.863,308.426 534.961,309.328 ; 535.863,306.387 ccw(c537.093,306.387) 536.223,305.517 ; 536.144,305.31 536.144,305.437 536.144,308.654 ; 348.659,-142.837 347.337,-141.515 v1(336.773,-141.515) 337.015,-141.758 347.071,-141.758 348.454,-143.141 348.962,-143.141 ; 348.659,-142.837 348.962,-143.141 ; 348.659,-142.837 351.326,-142.837 351.897,-142.266 351.897,-133.503 v1@352.138,-133.262 ; 348.962,-143.141 349.23,-143.141 350.754,-143.141 351.516,-143.141 ; 351.516,-143.141 352.659,-143.141 ; 351.516,-143.141 352.138,-142.519 ; 352.138,-142.62 352.659,-143.141 ; 352.138,-142.62 352.138,-142.519 ; 352.138,-142.519 352.138,-142.393 v1@352.138,-133.262 ; 352.926,-141.377 352.926,-128.931 ; 352.926,-141.377 352.926,-141.657 353.415,-142.145 ; 362.287,293.758 360.965,295.08 v1(350.401,295.08) 350.644,294.837 360.7,294.837 362.083,293.454 362.591,293.454 ; 362.287,293.758 362.591,293.454 ; 362.287,293.758 364.954,293.758 365.526,294.329 365.526,303.092 v1@365.767,303.333 ; 362.591,293.454 362.859,293.454 364.383,293.454 365.145,293.454 ; 362.819,-127.026 362.832,-127.039 380.993,-127.039 381.515,-127.561 ; 364.713,-150.913 v1(362.853,-150.913) 363.118,-150.648 364.47,-150.648 364.851,-150.267 364.851,-147.727 v1(365.232,-147.346) ; 364.713,-150.913 365.232,-150.394 v1(365.232,-147.346) ; 364.713,-150.913 365.348,-150.913 365.613,-150.648 365.613,-147.854 366.003,-147.465 366.003,-147.084 ; 365.145,293.454 366.288,293.454 ; 365.145,293.454 365.767,294.076 ; v1(365.232,-147.346) 365.74,-147.346 366.003,-147.084 ; 365.767,293.975 366.288,293.454 ; 365.767,293.975 365.767,294.076 ; 365.767,294.076 365.767,294.202 v1@365.767,303.333 ; 366.555,295.218 366.555,307.664 ; 366.555,295.218 366.555,294.938 367.043,294.45 ; 376.448,309.569 376.461,309.556 394.622,309.556 395.144,309.035 ; 378.341,285.682 v1(376.482,285.682) 376.747,285.947 378.099,285.947 378.48,286.328 378.48,288.868 v1(378.861,289.249) ; 378.341,285.682 378.861,286.201 v1(378.861,289.249) ; 378.341,285.682 378.976,285.682 379.242,285.947 379.242,288.741 379.631,289.131 379.631,289.512 ; v1(378.861,289.249) 379.369,289.249 379.631,289.512 ; 380.332,-127.267 380.84,-127.267 381.515,-127.942 ; 381.515,-127.942 381.515,-127.561 ; 393.961,309.328 394.469,309.328 395.144,308.654 ; 395.144,308.654 395.144,309.035 ; 489.659,-142.837 488.337,-141.515 v1(477.773,-141.515) 478.015,-141.758 488.071,-141.758 489.454,-143.141 489.962,-143.141 ; 489.659,-142.837 489.962,-143.141 ; 489.659,-142.837 492.326,-142.837 492.897,-142.266 492.897,-133.503 v1@493.138,-133.262 ; 489.962,-143.141 490.23,-143.141 491.754,-143.141 492.516,-143.141 ; 492.516,-143.141 493.659,-143.141 ; 492.516,-143.141 493.138,-142.519 ; 493.138,-142.62 493.659,-143.141 ; 493.138,-142.62 493.138,-142.519 ; 493.138,-142.519 493.138,-142.393 v1@493.138,-133.262 ; 493.926,-141.377 493.926,-128.931 ; 493.926,-141.377 493.926,-141.657 494.415,-142.145 ; 503.287,293.758 501.965,295.08 v1(491.401,295.08) 491.644,294.837 501.7,294.837 503.083,293.454 503.591,293.454 ; 503.287,293.758 503.591,293.454 ; 503.287,293.758 505.954,293.758 506.526,294.329 506.526,303.092 v1@506.767,303.333 ; 503.591,293.454 503.859,293.454 505.383,293.454 506.145,293.454 ; 503.819,-127.026 503.832,-127.039 521.993,-127.039 522.515,-127.561 ; 505.713,-150.913 v1(503.853,-150.913) 504.118,-150.648 505.47,-150.648 505.851,-150.267 505.851,-147.727 v1(506.232,-147.346) ; 505.713,-150.913 506.232,-150.394 v1(506.232,-147.346) ; 505.713,-150.913 506.348,-150.913 506.613,-150.648 506.613,-147.854 507.003,-147.465 507.003,-147.084 ; 506.145,293.454 507.288,293.454 ; 506.145,293.454 506.767,294.076 ; v1(506.232,-147.346) 506.74,-147.346 507.003,-147.084 ; 506.767,293.975 507.288,293.454 ; 506.767,293.975 506.767,294.076 ; 506.767,294.076 506.767,294.202 v1@506.767,303.333 ; 507.555,295.218 507.555,307.664 ; 507.555,295.218 507.555,294.938 508.043,294.45 ; 517.448,309.569 517.461,309.556 535.622,309.556 536.144,309.035 ; 519.341,285.682 v1(517.482,285.682) 517.747,285.947 519.099,285.947 519.48,286.328 519.48,288.868 v1(519.861,289.249) ; 519.341,285.682 519.861,286.201 v1(519.861,289.249) ; 519.341,285.682 519.976,285.682 520.242,285.947 520.242,288.741 520.631,289.131 520.631,289.512 ; v1(519.861,289.249) 520.369,289.249 520.631,289.512 ; 521.332,-127.267 521.84,-127.267 522.515,-127.942 ; 522.515,-127.942 522.515,-127.561 ; 534.961,309.328 535.469,309.328 536.144,308.654 ; 536.144,308.654 536.144,309.035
